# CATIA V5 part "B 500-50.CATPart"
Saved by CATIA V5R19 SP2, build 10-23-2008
Part number: B 500-50
Bounding box of the stored display mesh (mm): x -18.951 to 18.951, y -18.952 to 18.952, z 0 to 150
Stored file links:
  C:\Users\Bora\Desktop\3D Katı model\B serisi\B 500\B 500-50.CATPart
  C:\Program Files\Dassault Systemes\B19\intel_a\reffiles\standard\MetricThickPitch.txt
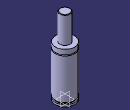
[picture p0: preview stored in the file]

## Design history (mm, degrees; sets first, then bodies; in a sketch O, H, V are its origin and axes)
Body1 (main body)
  Sketch1 on yz-plane, origin (0, 0, 0), H (0, 1, 0), V (0, 0, 1)
    point P3 (10, 149)
    point P5 (10, 149)
    point P7 (19, 88.5)
    point P8 (19, 86.5)
    point P12 (19, 86.5)
    point P13 (19, 88.5)
    line L1 (19, 0) -> (19, 4)
    line L2 (10, 149) -> (10, 98)
    arc A1 centre (9, 149) radius 1 from (10, 149) to (9, 150) ccw
    arc A2 centre (19, 87.5) radius 1 from (19, 88.5) to (19, 86.5) ccw
    line L3 (16.5, 7.5) -> (16.5, 4)
    line L4 (19, 7.5) -> (19, 86.5)
    line L5 (19, 88.5) -> (19, 98)
    line L6 (9, 150) -> (0, 150)
    point P15 (0, 150)
    line L7 (10, 98) -> (19, 98)
    line L8 (0, 0) -> (19, 0)
    line L9 (16.5, 7.5) -> (19, 7.5)
    line L10 (16.5, 4) -> (19, 4)
    coincidence: P15 V, P3 P5, P7 P13, P8 P12
    tangency: L6 A1
    horizontal: L7 H, L8 H, L9 H, L10 H
  Shaft1: profile Sketch1, axis Sketch1.V, angle 360
  Sketch2 on face of Shaft1 from Sketch1.L8, origin (0, 0, 0), H (1, 0, 0), V (0, -1, 0)
    point P1 (0, 0)
  Hole1: placed by Sketch2, at (0, 0, 0) direction (0, 0, 1), diameter 6.647, depth 7, threaded "M8", thread diameter 8, thread depth 7, pitch 1.25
